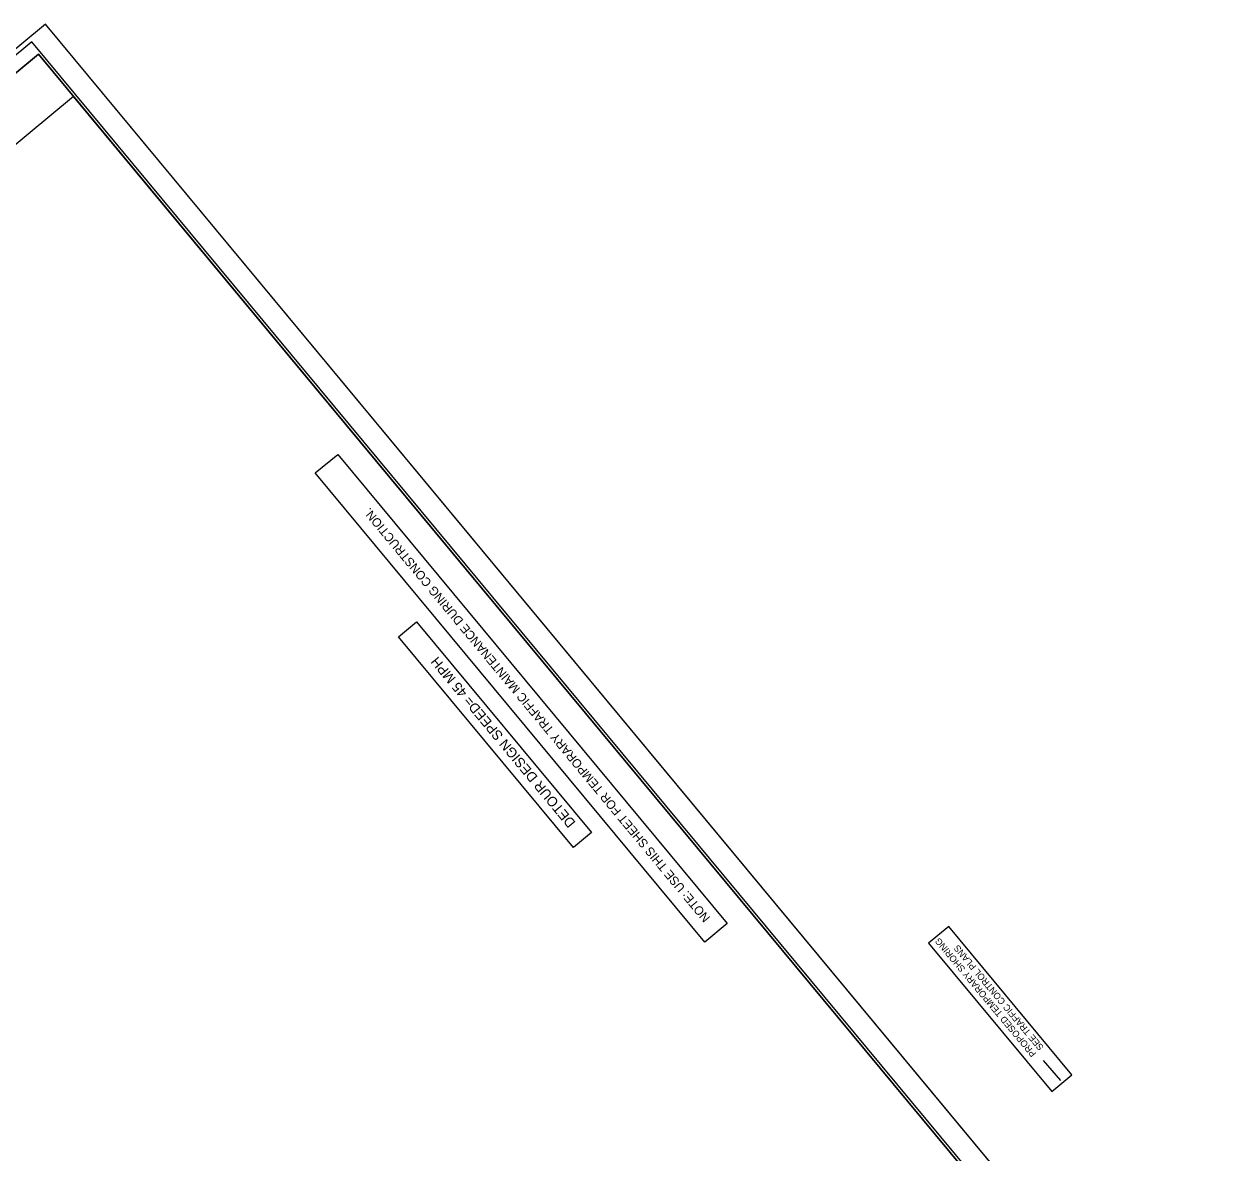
# Model space of a CAD drawing. Extents: x 2597036 to 2598995, y 852197 to 854192.
# Drawn here: x 2597900 to 2598995, y 853163 to 854192 of the extents above; entities that cross this region are included whole.
import ezdxf

# ---------------------------------------------------------------- set-up
doc = ezdxf.new("R2010")
doc.units = 0
for name, color, linetype in [('Old_Level_1', 7, 'Continuous'), ('Old_Level_30', 7, 'Continuous'), ('Prop Dimension Text', 7, 'Continuous'), ('Prop Hatching', 7, 'Continuous'), ('Prop Horizontal Alignment Curve and Spiral Data', 7, 'Continuous'), ('Sheet Clip Boundary CELL', 7, 'Continuous'), ('Sheet Cutting Line CELL', 7, 'Continuous'), ('Sheet Plan CELL', 7, 'Continuous'), ('Sheet Plan Layout CELL', 7, 'Continuous'), ('Sheet Plot Border Inside CELL', 7, 'Continuous'), ('Sheet Plot Border Outside CELL', 7, 'Continuous')]:
    doc.layers.add(name, color=color, linetype=linetype)

msp = doc.modelspace()

# ---------------------------------------------------------------- linework, layer by layer
at = {"layer": 'Old_Level_1'}
msp.add_lwpolyline([(2598520.5, 853355.4), (2598165.6, 853782.7), (2598186, 853799.6), (2598540.8, 853372.2)], close=True, dxfattribs=at)
at = {"layer": 'Old_Level_30'}
msp.add_line((2598828.9, 853247.5), (2598844.5, 853229.3), dxfattribs=at)
at = {"layer": 'Prop Hatching'}
msp.add_lwpolyline([(2598855, 853234.5), (2598742.8, 853369.7), (2598724.4, 853354.4), (2598836.7, 853219.2)], close=True, dxfattribs=at)
at = {"layer": 'Prop Horizontal Alignment Curve and Spiral Data'}
msp.add_lwpolyline([(2598400.8, 853441.6), (2598241.4, 853633.5), (2598257.9, 853647.2), (2598417.2, 853455.3)], close=True, dxfattribs=at)
at = {"layer": 'Sheet Clip Boundary CELL'}
msp.add_lwpolyline([(2598839.7, 853048.6), (2597945.3, 854125.7), (2597300.2, 853590), (2597421.1, 853444.4), (2597258.4, 853309.3), (2598031.9, 852377.8)], close=True, dxfattribs=at)
at = {"layer": 'Sheet Cutting Line CELL'}
msp.add_line((2598995.3, 852896.4), (2597919.8, 854191.6), dxfattribs=at)
at = {"layer": 'Sheet Plan CELL'}
for points in [[(2597105.5, 853493.4), (2598063.8, 852339.3), (2598871.6, 853010.1), (2597913.3, 854164.1)], [(2598871.6, 853010.1), (2598063.9, 852339.3), (2597233.3, 853339.4), (2597348.8, 853435.3), (2597221, 853589.2), (2597913.3, 854164.1)]]:
    msp.add_lwpolyline(points, close=True, dxfattribs=at)
at = {"layer": 'Sheet Plan Layout CELL'}
msp.add_lwpolyline([(2598063.9, 852339.3), (2598871.6, 853010.1), (2597913.3, 854164.1), (2597268.3, 853628.4), (2597421.1, 853444.4), (2597258.4, 853309.3)], close=True, dxfattribs=at)
at = {"layer": 'Sheet Plot Border Inside CELL'}
msp.add_lwpolyline([(2598971.6, 852893.7), (2597907.3, 854175.3), (2597095.6, 853501.4), (2598160, 852219.7)], close=True, dxfattribs=at)
at = {"layer": 'Sheet Plot Border Outside CELL'}
msp.add_lwpolyline([(2598995.3, 852896.4), (2597919.8, 854191.6), (2597077.4, 853492.1), (2598152.9, 852196.9)], close=True, dxfattribs=at)

# ---------------------------------------------------------------- texts
at = {"layer": 'Old_Level_1'}
msp.add_text('NOTE: USE THIS SHEET FOR TEMPORARY TRAFFIC MAINTENANCE DURING CONSTRUCTION.', height=8, rotation=129.7066, dxfattribs=at).set_placement((2598525.8, 853377.6))
at = {"layer": 'Prop Dimension Text'}
for s, p in [('PROPOSED TEMPORARY SHORING', (2598822.8, 853253.9)), ('SEE TRAFFIC CONTROL PLANS', (2598829.7, 853259.7))]:
    msp.add_text(s, height=6, rotation=129.8902, dxfattribs=at).set_placement(p)
at = {"layer": 'Prop Horizontal Alignment Curve and Spiral Data'}
msp.add_text('DETOUR DESIGN SPEED= 45 MPH  ', height=8.96, rotation=129.7066, dxfattribs=at).set_placement((2598403.2, 853464.3))

doc.saveas('drawing.dxf')
